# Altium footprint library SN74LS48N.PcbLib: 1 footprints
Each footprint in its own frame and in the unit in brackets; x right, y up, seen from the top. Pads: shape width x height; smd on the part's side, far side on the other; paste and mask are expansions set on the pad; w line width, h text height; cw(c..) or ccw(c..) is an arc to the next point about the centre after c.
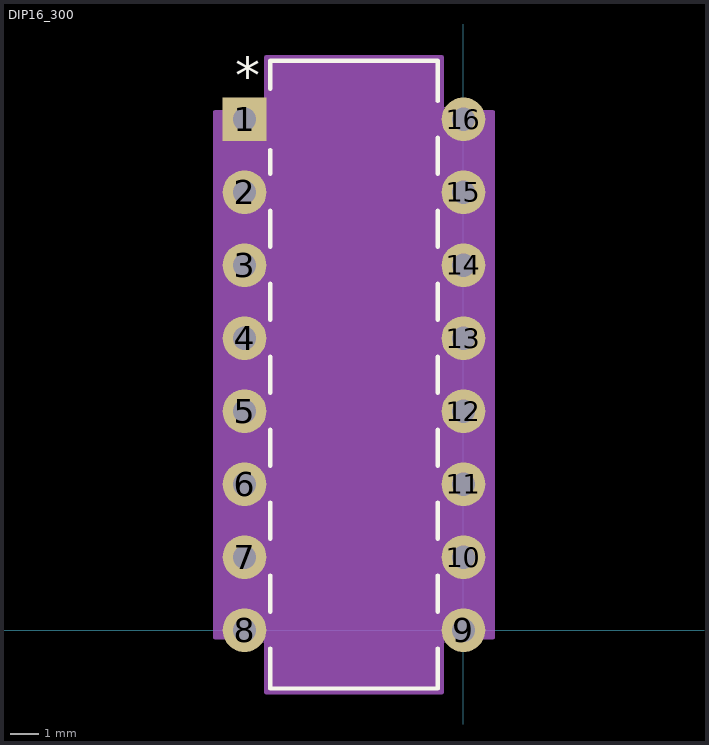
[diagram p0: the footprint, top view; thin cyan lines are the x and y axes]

## DIP16_300 [mil]
pads (16):
  rect 60x60 hole 32 paste-30 mask-30: 1(-300,700)
  round 60 hole 32 paste-30 mask-30: 2(-300,600) 3(-300,500) 4(-300,400) 5(-300,300) 6(-300,200) 7(-300,100) 8(-300,0) 9(0,0) 10(0,100) 11(0,200) 12(0,300) 13(0,400) 14(0,500) 15(0,600) 16(0,700)
Top Overlay:
  lines w6: -265,-25.15 -265,-80 -35,-80 -35,-25.15 ; -265,25.15 -265,74.85 ; -265,125.15 -265,174.85 ; -265,225.15 -265,274.85 ; -265,325.15 -265,374.85 ; -265,425.15 -265,474.85 ; -265,525.15 -265,574.85 ; -265,625.15 -265,657.89 ; -265,742.11 -265,780 -35,780 -35,725.15 ; -35,25.15 -35,74.85 ; -35,125.15 -35,174.85 ; -35,225.15 -35,274.85 ; -35,325.15 -35,374.85 ; -35,425.15 -35,474.85 ; -35,525.15 -35,574.85 ; -35,625.15 -35,674.85
  text "*" at -312.5,735 h50
  text ".Designator" at -287.5,325 h50
Mechanical 13:
  lines w1: -162,775 ccw(c-150,775) -138,775 ; -316,-16 -316,16 -260,16 -260,-16 -316,-16 ; -316,84 -316,116 -260,116 -260,84 -316,84 ; -316,184 -316,216 -260,216 -260,184 -316,184 ; -316,284 -316,316 -260,316 -260,284 -316,284 ; -316,384 -316,416 -260,416 -260,384 -316,384 ; -316,484 -316,516 -260,516 -260,484 -316,484 ; -316,584 -316,616 -260,616 -260,584 -316,584 ; -316,684 -316,716 -260,716 -260,684 -316,684 ; -260,-75 -40,-75 -40,775 -260,775 -260,-75 ; -40,-16 -40,16 16,16 16,-16 -40,-16 ; -40,84 -40,116 16,116 16,84 -40,84 ; -40,184 -40,216 16,216 16,184 -40,184 ; -40,284 -40,316 16,316 16,284 -40,284 ; -40,384 -40,416 16,416 16,384 -40,384 ; -40,484 -40,516 16,516 16,484 -40,484 ; -40,584 -40,616 16,616 16,584 -40,584 ; -40,684 -40,716 16,716 16,684 -40,684
  text ".Designator" at -287.5,325 h50
  text "*" at -262.5,675 h50
Mechanical 15:
  region: -30,-10 40,-10 40,710 -30,710 -30,785 -270,785 -270,710 -340,710 -340,-10 -270,-10 -270,-85 -30,-85
  lines w6: -340,-10 -340,710 -270,710 -270,785 -30,785 -30,710 40,710 40,-10 -30,-10 -30,-85 -270,-85 -270,-10 -340,-10
3D body "DIP16_300.step": height 205.12, standoff -100, extent -5,-775 315,75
